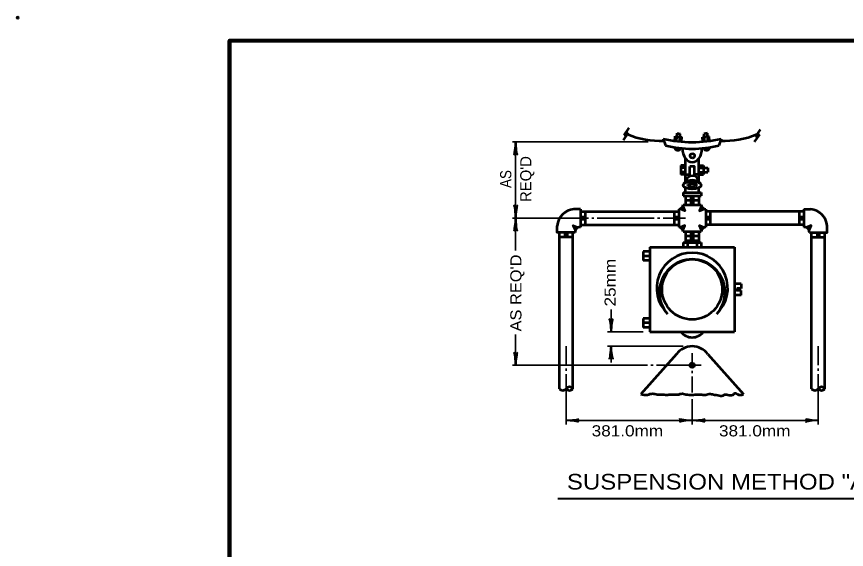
# Model space of a CAD drawing. Extents: x -35 to 821, y -10 to 534.
# Drawn here: x -34.6 to 188.7, y 390.4 to 533.8 of the extents above; entities that cross this region are included whole.
import ezdxf
from ezdxf.enums import TextEntityAlignment as Align

# ---------------------------------------------------------------- set-up
doc = ezdxf.new("R2010")
doc.units = 0
doc.header["$LTSCALE"] = 1.2
doc.header["$PDMODE"] = 32
doc.header["$PDSIZE"] = 0.6
doc.layers.add('1', color=7, linetype='Continuous', lineweight=35)

msp = doc.modelspace()

# ---------------------------------------------------------------- linework, layer by layer
at = {"layer": '1', "lineweight": 53}
for p, q in [((128.696, 500.511), (130.073, 502.477)), ((128.879, 501.83), (130.256, 503.796)), ((128.879, 501.83), (130.073, 502.477)), ((165.473, 503.347), (164.097, 501.381)), ((139.39, 500.882), (139.99, 499.082)), ((142.491, 500.306), (142.598, 501.531)), ((142.598, 501.531), (144.382, 501.289)), ((142.942, 500.296), (143.125, 502.388)), ((143.125, 502.388), (143.995, 502.219)), ((143.849, 500.124), (143.995, 502.219)), ((144.299, 500.105), (144.382, 501.289)), ((151.803, 501.487), (150.002, 501.287)), ((150.084, 500.105), (150.002, 501.287)), ((151.291, 502.353), (150.388, 502.216)), ((150.534, 500.121), (150.388, 502.216)), ((151.438, 500.259), (151.291, 502.353)), ((151.885, 500.306), (151.803, 501.487)), ((154.99, 500.882), (154.39, 499.082)), ((165.291, 502.028), (163.914, 500.062)), ((165.291, 502.028), (164.097, 501.381)), ((145.363, 493.682), (144.163, 493.682)), ((144.163, 493.682), (144.163, 491.282)), ((145.363, 489.239), (145.363, 495.611)), ((149.017, 489.239), (149.017, 495.611)), ((149.017, 493.682), (150.217, 493.682)), ((150.217, 493.682), (150.217, 491.282)), ((145.363, 493.082), (144.163, 493.082)), ((145.363, 491.882), (144.163, 491.882)), ((145.363, 491.282), (144.163, 491.282)), ((145.363, 491.282), (146.563, 491.282)), ((146.563, 491.282), (146.563, 493.382)), ((149.017, 491.282), (147.817, 491.282)), ((149.017, 493.082), (151.417, 493.082)), ((149.017, 491.882), (151.417, 491.882)), ((149.017, 491.282), (150.217, 491.282)), ((151.417, 493.082), (151.417, 491.882)), ((145.363, 486.413), (145.363, 487.682)), ((149.017, 486.413), (149.017, 487.682)), ((144.763, 486.413), (149.617, 486.413)), ((144.763, 486.413), (144.763, 485.513)), ((144.763, 485.513), (149.617, 485.513)), ((145.363, 485.513), (145.363, 483.113)), ((146.563, 484.913), (147.817, 484.913)), ((149.017, 485.513), (149.017, 483.113)), ((149.617, 486.413), (149.617, 485.513)), ((144.763, 483.113), (149.617, 483.113)), ((145.363, 484.313), (149.017, 484.313)), ((146.563, 483.713), (147.817, 483.713)), ((117.163, 481.913), (115.363, 481.913)), ((117.163, 481.913), (117.163, 477.113)), ((117.163, 481.313), (143.563, 481.313)), ((118.363, 481.313), (118.363, 477.713)), ((142.363, 481.313), (142.363, 477.713)), ((143.563, 481.921), (143.563, 477.113)), ((150.821, 481.921), (150.821, 477.106)), ((177.221, 481.313), (150.821, 481.313)), ((152.02, 481.313), (152.02, 477.713)), ((176.02, 481.313), (176.02, 477.713)), ((177.221, 481.913), (177.221, 477.113)), ((177.221, 481.913), (179.02, 481.913)), ((117.763, 480.113), (117.763, 478.913)), ((142.963, 480.113), (142.963, 478.913)), ((151.421, 480.113), (151.421, 478.913)), ((176.621, 480.113), (176.621, 478.913)), ((117.163, 477.713), (143.563, 477.713)), ((144.772, 475.913), (149.613, 475.913)), ((145.372, 475.913), (145.372, 472.913)), ((149.013, 475.913), (149.013, 472.913)), ((177.221, 477.713), (150.821, 477.713)), ((111.463, 433.613), (111.463, 475.613)), ((115.063, 474.413), (111.463, 474.413)), ((113.863, 475.013), (112.663, 475.013)), ((115.063, 433.613), (115.063, 475.613)), ((145.372, 474.713), (149.013, 474.713)), ((145.372, 473.513), (149.013, 473.513)), ((146.572, 475.313), (147.813, 475.313)), ((146.572, 474.113), (147.813, 474.113)), ((179.321, 433.613), (179.321, 475.613)), ((179.321, 474.413), (182.921, 474.413)), ((180.52, 475.013), (181.721, 475.013)), ((182.921, 433.613), (182.921, 475.613)), ((135.772, 471.713), (158.613, 471.713)), ((135.772, 471.713), (135.772, 448.913)), ((144.772, 472.913), (149.613, 472.913)), ((144.772, 472.913), (144.772, 471.713)), ((145.972, 472.913), (145.972, 471.713)), ((146.572, 472.949), (147.813, 472.949)), ((148.413, 472.913), (148.413, 471.713)), ((149.613, 472.913), (149.613, 471.713)), ((158.613, 471.713), (158.613, 448.913)), ((135.772, 470.513), (133.972, 470.513)), ((133.972, 470.513), (133.972, 468.113)), ((135.772, 469.313), (133.972, 469.313)), ((135.772, 468.113), (133.972, 468.113)), ((160.413, 461.813), (158.613, 461.813)), ((160.413, 460.613), (159.213, 460.613)), ((160.413, 461.813), (160.413, 460.613)), ((160.413, 458.813), (158.613, 458.813)), ((160.413, 458.813), (160.413, 460.013)), ((135.772, 452.513), (133.972, 452.513)), ((133.972, 452.513), (133.972, 450.113)), ((135.772, 451.313), (133.972, 451.313)), ((135.772, 450.113), (133.972, 450.113)), ((135.772, 448.913), (158.613, 448.913)), ((142.972, 442.913), (133.372, 432.113)), ((151.413, 442.913), (161.013, 432.113))]:
    msp.add_line(p, q, dxfattribs=at)
at = {"layer": '1'}
for p, q in [((135.323, 500.009), (98.863, 500.009)), ((99.688, 479.513), (99.688, 500.009)), ((119.263, 479.513), (98.863, 479.513)), ((99.688, 479.513), (99.688, 470.799)), ((120.763, 479.513), (120.163, 479.513)), ((136.963, 479.513), (121.663, 479.513)), ((138.463, 479.513), (137.863, 479.513)), ((145.363, 479.513), (139.363, 479.513)), ((125.361, 448.913), (125.361, 454.921)), ((133.972, 448.913), (124.392, 448.913)), ((99.688, 448.198), (99.688, 439.913)), ((113.263, 445.013), (113.263, 439.913)), ((144.792, 445.013), (124.392, 445.013)), ((125.361, 445.013), (125.361, 440.7)), ((181.126, 445.013), (181.126, 439.913)), ((147.192, 443.213), (147.192, 439.313)), ((98.863, 439.913), (135.192, 439.913)), ((113.263, 439.013), (113.263, 438.413)), ((136.092, 439.913), (136.692, 439.913)), ((137.592, 439.913), (149.592, 439.913)), ((147.192, 438.413), (147.192, 437.813)), ((181.126, 439.013), (181.126, 438.413)), ((113.263, 437.513), (113.263, 424.013)), ((147.192, 436.913), (147.192, 432.587)), ((181.126, 437.513), (181.126, 424.013)), ((147.192, 430.787), (147.192, 424.013))]:
    msp.add_line(p, q, dxfattribs=at)
at = {"layer": '1', "lineweight": 40}
msp.add_line((111.055, 404.049), (281.348, 404.049), dxfattribs=at)
at = {"layer": '1', "lineweight": 158}
msp.add_lwpolyline([(814.384, 527.35), (22.684, 527.25), (22.784, 1.25)], dxfattribs=at)
at = {"layer": '1', "lineweight": 53}
for points in [[(147.817, 491.282), (147.817, 493.382), (146.563, 493.382)], [(144.667, 482.73), (145.249, 481.474), (143.939, 482.011)], [(149.713, 482.73), (149.131, 481.474), (150.441, 482.011)], [(115.663, 475.613), (110.863, 475.613), (110.863, 477.413)], [(115.752, 476.312), (115.17, 477.568), (116.479, 477.031)], [(144.675, 476.303), (145.257, 477.559), (143.947, 477.022)], [(149.709, 476.296), (149.127, 477.552), (150.436, 477.015)], [(178.632, 476.312), (179.214, 477.568), (177.905, 477.031)], [(178.721, 475.613), (183.52, 475.613), (183.52, 477.413)], [(160.413, 460.013), (159.213, 460.013), (159.213, 460.613)]]:
    msp.add_lwpolyline(points, dxfattribs=at)
at = {"layer": '1'}
msp.add_lwpolyline([(113.263, 425.08), (147.192, 425.08), (181.126, 425.08)], dxfattribs=at)
at = {"layer": '1', "lineweight": 53}
for centre, radius in [((147.244, 496.29), 0.6), ((147.18, 460.327), 8.1), ((147.191, 439.914), 0.6)]:
    msp.add_circle(centre, radius, dxfattribs=at)
for centre, radius, start, end in [((138.81, 524.024), 23.724, 247.65241, 271.85853), ((147.19, 534.232), 34.25, 256.83593, 283.1638), ((155.57, 524.024), 23.724, 268.14138, 292.34759), ((147.19, 527.432), 29.25, 255.74997, 284.25003), ((143.304, 498.797), 0.986, 192.33045, 332.21364), ((151.08, 498.798), 0.986, 207.78636, 347.66955), ((147.19, 489.079), 1.834, 4.98578, 175.01422), ((143.445, 483.239), 1.324, 291.91656, 354.5292), ((143.445, 483.239), 1.324, 291.91738, 337.37313), ((150.935, 483.239), 1.324, 185.4708, 248.08344), ((150.935, 483.239), 1.324, 202.62687, 248.08262), ((115.716, 477.06), 4.866, 94.15966, 175.84035), ((143.445, 483.239), 1.324, 275.11437, 291.91656), ((150.935, 483.239), 1.324, 248.08344, 265.0377), ((178.668, 477.06), 4.866, 4.15965, 85.84034), ((116.973, 475.803), 1.324, 111.91656, 188.24718), ((116.973, 475.803), 1.324, 111.91738, 157.37313), ((116.973, 475.803), 1.324, 81.75282, 111.91656), ((143.453, 475.794), 1.324, 68.08344, 85.22882), ((143.453, 475.794), 1.324, 5.16652, 68.08344), ((143.453, 475.794), 1.324, 22.62687, 68.08262), ((150.931, 475.787), 1.324, 111.91656, 174.5292), ((150.931, 475.787), 1.324, 111.91738, 157.37313), ((150.931, 475.787), 1.324, 94.77118, 111.91656), ((177.41, 475.803), 1.324, 68.08344, 98.24718), ((177.41, 475.803), 1.324, 351.75282, 68.08344), ((177.41, 475.803), 1.324, 22.62687, 68.08262), ((147.192, 460.643), 9.57, 313.60282, 226.39718), ((147.192, 459.59), 8.837, 318.31863, 221.68137), ((147.192, 451.204), 3.791, 217.18292, 322.81708), ((147.192, 439.722), 5.291, 37.09384, 142.90616), ((112.363, 434.243), 1.099, 215.00672, 324.99328), ((114.163, 432.982), 1.099, 35.00672, 144.99328), ((114.163, 434.243), 1.099, 215.00672, 324.99328), ((180.221, 434.243), 1.099, 215.00672, 324.99328), ((182.021, 432.982), 1.099, 35.00672, 144.99328), ((182.021, 434.243), 1.099, 215.00672, 324.99328)]:
    msp.add_arc(centre, radius, start, end, dxfattribs=at)
at = {"layer": '1', "lineweight": 40}
for centre, major_axis, ratio, start_param, end_param in [((99.434, 498.665), (0.211, 2.108), 0.07063, 3.1407148, 5.41811), ((100.019, 498.7), (-0.187, 2.143), 0.122415, 0.8963533, 3.1415927), ((99.356, 480.823), (0.187, -2.143), 0.122415, 0.8963533, 3.1415927), ((99.942, 480.858), (-0.211, -2.108), 0.07063, 3.1407148, 5.41811), ((99.434, 478.168), (0.211, 2.108), 0.07063, 3.1407148, 5.41811), ((99.434, 478.168), (0.211, 2.108), 0.07063, 3.1407148, 5.41811), ((100.019, 478.204), (-0.187, 2.143), 0.122415, 0.8963533, 3.1415927), ((100.019, 478.204), (-0.187, 2.143), 0.122415, 0.8963533, 3.1415927), ((125.03, 450.223), (0.187, -2.143), 0.122415, 0.8963533, 3.1415927), ((125.615, 450.258), (-0.211, -2.108), 0.07063, 3.1407148, 5.41811), ((125.107, 443.668), (0.211, 2.108), 0.07063, 3.1407148, 5.41811), ((125.693, 443.704), (-0.187, 2.143), 0.122415, 0.8963533, 3.1415927), ((99.356, 441.223), (0.187, -2.143), 0.122415, 0.8963533, 3.1415927), ((99.356, 441.223), (0.187, -2.143), 0.122415, 0.8963533, 3.1415927), ((99.942, 441.258), (-0.211, -2.108), 0.07063, 3.1407148, 5.41811), ((99.942, 441.258), (-0.211, -2.108), 0.07063, 3.1407148, 5.41811), ((114.608, 424.826), (-2.108, 0.211), 0.07063, 3.1407148, 5.41811), ((114.573, 425.411), (-2.143, -0.187), 0.122415, 0.8963533, 3.1415927), ((145.883, 424.748), (2.143, 0.187), 0.122415, 0.8963533, 3.1415927), ((145.848, 425.334), (2.108, -0.211), 0.07063, 3.1407148, 5.41811), ((148.537, 424.826), (-2.108, 0.211), 0.07063, 3.1407148, 5.41811), ((148.502, 425.411), (-2.143, -0.187), 0.122415, 0.8963533, 3.1415927), ((179.816, 424.748), (2.143, 0.187), 0.122415, 0.8963533, 3.1415927), ((179.781, 425.334), (2.108, -0.211), 0.07063, 3.1407148, 5.41811)]:
    msp.add_ellipse(centre, major_axis=major_axis, ratio=ratio, start_param=start_param, end_param=end_param, dxfattribs=at)
at = {"layer": '1', "lineweight": 53}
for centre, major_axis, ratio, start_param, end_param in [((147.19, 498.482), (0, 3.9), 0.692308, 1.615522, 4.6676498), ((147.19, 488.363), (2.4, 0), 0.5625, 6.2831853, 9.424778)]:
    msp.add_ellipse(centre, major_axis=major_axis, ratio=ratio, start_param=start_param, end_param=end_param, dxfattribs=at)
for major_axis, ratio in [((2.4, 0), 0.4375), ((1.2, 0), 0.375)]:
    msp.add_ellipse((147.19, 488.363), major_axis=major_axis, ratio=ratio, dxfattribs=at)
msp.add_spline([(133.372, 432.113), (135.158, 431.987), (136.632, 432.295), (137.73, 432.055), (139.273, 432.021), (140.678, 431.987), (141.638, 432.055), (143.593, 432.089), (144.244, 432.261), (145.513, 432.089), (147.261, 431.987), (148.495, 432.021), (149.798, 432.021), (150.895, 431.987), (151.41, 432.124), (152.13, 432.192), (153.192, 431.987), (154.049, 431.849), (155.49, 431.815), (155.764, 431.952), (156.792, 431.952), (158.027, 431.918), (158.267, 432.055), (158.884, 432.432), (159.364, 432.124), (161.013, 432.113)], degree=3, dxfattribs=at)
at = {"layer": '1'}
msp.add_point((-34.316, 533.45), dxfattribs=at)

# ---------------------------------------------------------------- texts
msp.add_text("REQ'D", height=3, rotation=90, dxfattribs=at).set_placement((103.912, 490.026), align=Align.CENTER)
at = {"layer": '1', "width": 0.9}
msp.add_text('AS', height=3, rotation=90, dxfattribs=at).set_placement((98.512, 490.026), align=Align.CENTER)
at = {"layer": '1'}
for s, width, p in [("AS REQ'D", 1.1, (101.245, 449.016)), ('25mm', 1.15, (126.6, 455.738))]:
    msp.add_text(s, height=3, rotation=90, dxfattribs=dict(at, width=width)).set_placement(p)
at = {"layer": '1', "width": 1.15}
for s, height, p in [('381.0mm', 3, (120.141, 420.771)), ('381.0mm', 3, (154.409, 420.771)), ('SUSPENSION METHOD "A" - SINGLE HANGER UNITS', 4.2, (113.481, 406.476))]:
    msp.add_text(s, height=height, dxfattribs=at).set_placement(p)

doc.saveas('drawing.dxf')
